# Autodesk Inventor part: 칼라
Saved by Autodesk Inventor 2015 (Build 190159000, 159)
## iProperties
Created: 2025-08
Part Number: 칼라
Material: 일반
Document SubType Name: Modeling
Designer: user
Density: 1 g/cm^3
Appearance: 기본값
Author: user
Author: jhkim
Creation Date: 2025-08-05
Sending System: Autodesk Inventor 2026
Preprocessor: ST-DEVELOPER v20.1
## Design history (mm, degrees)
node "칼라1"
node "솔리드1"
node "기준1"
